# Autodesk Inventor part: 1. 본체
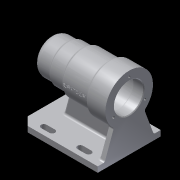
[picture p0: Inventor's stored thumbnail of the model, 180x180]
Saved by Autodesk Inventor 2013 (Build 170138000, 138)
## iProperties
Created: 2017-09
Part Number: 1. 본체
Material: 알루미늄 6061
Document SubType Name: Modeling
Designer: Administrator
Mass: 706.135 g
Surface Area: 708.39 cm^2
Volume: 260.566 cm^3
Density: 2.71 g/cm^3
Author: Administrator
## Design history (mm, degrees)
sketch "스케치1"
  geometry: L1 (-56, 0)-(56, 0); L2 (-56, 0)-(-56, 25); L3 (-56, 25)-(-31, 25); L4 (-31, 25)-(-31, 27); L5 (-31, 27)-(-11, 27); L6 (-11, 27)-(-11, 30); L7 (-11, 30)-(28, 30); L8 (28, 30)-(28, 34); L9 (28, 34)-(56, 34); L10 (56, 34)-(56, 0); L11 (-50, 0)-(-50, 10.5); L12 (-50, 10.5)-(-47, 10.5); L13 (-47, 10.5)-(-47, 16); L14 (-47, 16)-(-43, 16); L15 (-43, 16)-(-43, 17.5); L16 (-43, 17.5)-(-25, 17.5); L17 (-25, 17.5)-(-25, 21); L18 (-25, 21)-(-13, 21); L19 (-13, 21)-(-13, 24); L20 (-13, 24)-(41, 24); L21 (41, 24)-(41, 21); L22 (41, 21)-(56, 21); 2 further points
  constraints: 44 end point, 15 parallel, 6 perpendicular, 2 point on line, 1 coincident, 1 collinear, 1 horizontal, 1 midpoint
  dimensions: "d0" = 112 distance of L1.start L1.end; "d2" = 42 diameter of L22 L1; "d3" = 48 diameter of L20 L1; "d4" = 35 diameter of L16 L1; "d5" = 32 diameter of L14 L1; "d6" = 21 diameter of L12 L1; "d7" = 50 diameter of L3 L1; "d8" = 54 diameter of L5 L1; "d9" = 60 diameter of L7 L1; "d11" = 68 diameter of L9 L1; "d12" = 15 distance between parallel lines of L21 L10; "d13" = 54 distance between parallel lines of L19 L21; "d14" = 12 distance between parallel lines of L17 L19; "d15" = 18 distance between parallel lines of L15 L17; "d16" = 4 distance between parallel lines of L13 L15; "d17" = 3 distance between parallel lines of L11 L13; "d18" = 84 distance between parallel lines of L8 L2; "d19" = 45 distance between parallel lines of L6 L2; "d20" = 25 distance between parallel lines of L4 L2
revolve "회전1" sketch "스케치1" stored, may be unused: angle "d21" = 90 deg
node "작업 평면1"
sketch "스케치2"
  geometry: L1 (-56, 34)-(-56, -34) reference; L2 (56, -45)-(-56, -45); L3 (-56, -45)-(-56, 45); L4 (-56, 45)-(56, 45); L5 (56, 45)-(56, -45); 2 further points
  constraints: 8 end point, 2 parallel, 1 horizontal, 1 horizontal alignment, 1 midpoint, 1 perpendicular, 1 point on line
  dimensions: "d23" = 90 distance between parallel lines of L4 L2; "d25" = 112 distance between parallel lines of L5 L1
extrude "돌출1" join sketch "스케치2" distance "d26" = 8; taper "d27" = 0 deg
sketch "스케치3"
  geometry: L1 (-45, -62)-(45, -62) reference; L2 (21.9, -26.008)-(35, -62); L3 (45, -70)-(45, -62) reference; L4 (0, 0)-(0, -62); L5 (-21.9, -26.008)-(-35, -62); L6 (-35, -62)-(35, -62); L7 (-45, -70)-(-45, -62) reference; A1 r 34 centre (0, 0) between (-21.9, -26.008) and (21.9, -26.008)
  constraints: 8 end point, 2 point on circle, 1 centre point, 1 coincident, 1 collinear, 1 midpoint, 1 point on line, 2 other
  dimensions: "d28" = 10 distance from line of L2.end L3; "d29" = 110 deg angle of L2 L1; "d90" = 10 distance from line of L5.end L7; "d91" = 110 deg angle of L5 L1
extrude "돌출2" join sketch "스케치3" distance "d30" = 8; taper "d31" = 0 deg
sketch "스케치5"
  geometry: L1 (-56, -62)-(56, -62) reference; L2 (-31, -27)-(-11, -27) reference; L3 (-34, -62)-(-24.622, -27); L4 (-56, -70)-(-56, -62) reference; 1 further point
  constraints: 2 end point, 2 point on line
  dimensions: "d34" = 22 distance from line of L3.start L4; "d35" = 105 deg angle of L3 L1
feature "리브1" sketch "스케치5" dims "d36" = 1, "d37" = 8, "d38" = 0, "d39" = 0, "d40" = 1, "d41" = 1
sketch "스케치6" dims "d52" = 10
  geometry: L1 (-56, -45)-(56, -45) reference; L2 (56, -45)-(56, -35) reference; L3 (48, -35)-(48, -4) reference; L4 (20, -30)-(32, -30); L5 (32, -38)-(20, -38); L6 (-20, -38)-(-32, -38); L7 (-32, -30)-(-20, -30); A1 r 4 centre (32, -34) between (32, -38) and (32, -30); A2 r 4 centre (20, -34) between (20, -30) and (20, -38); A3 r 4 centre (-20, -34) between (-20, -38) and (-20, -30); A4 r 4 centre (-32, -34) between (-32, -30) and (-32, -38); 1 further point
  constraints: 8 end point, 8 point on circle, 4 centre point, 4 tangent, 1 horizontal, 1 parallel, 1 perpendicular, 10 other
  dimensions: "d42" = 8 distance between parallel lines of L5 L4; "d44" = 34 vertical distance of A1.centre point (0, 0); "d45" = 24 distance from line of A1.centre L2; "d46" = 12 distance of A2.centre A1.centre; "d49" = 52 distance of A1.centre A3.centre
extrude "돌출3" cut sketch "스케치6" stored distance "d54" = 8; taper "d55" = 0 deg
chamfer "모따기1" distance "d56" = 12; stored, may be unused: second distance "d57" = 2, angle "d58" = 45 deg
fillet "모깎기1" dims "d59" = 3
fillet "모깎기2" dims "d60" = 3
fillet "모깎기3" dims "d61" = 3
fillet "모깎기4" dims "d66" = 9, "d67" = 3, "d68" = 0.3
chamfer "모따기2" distance "d69" = 1; stored, may be unused: second distance "d70" = 2, angle "d71" = 45 deg
fillet "모깎기5" dims "d72" = 3
node "작업 평면2"
sketch "스케치7"
  geometry: L1 (47.5, -24.711)-(47.5, 34) reference; L2 (47.5, -70)-(-52.5, -70) reference; 2 further points
  constraints: 1 other
  dimensions: "d73" = 48 distance from line of point (-0.5, 0) L1; "d74" = 70 distance from line of L2 point (-0.5, 0)
feature "엠보싱1" sketch "스케치7" dims "d0" = 112, "d2" = 42, "d3" = 48, "d4" = 35, "d5" = 32, "d6" = 21, "d7" = 50, "d8" = 54, "d9" = 60, "d11" = 68, "d12" = 15, "d13" = 54, "d14" = 12, "d15" = 18, "d16" = 4, "d17" = 3, "d18" = 84, "d19" = 45, "d20" = 25, "d75" = 0.5, "d76" = 0
sketch "스케치8" dims "d77" = 52
  geometry: C1 r 22 at (45, 70) reference; A1 r 34 centre (45, 70) between (68.353, 45.289) and (21.647, 45.289) reference; 2 further points
  constraints: 2 vertical alignment, 1 coincident, 2 other
hole "구멍1" sketch "스케치8" at (45, 96) diameter "d79" = 3.242; stored, may be unused: countersink angle "d83" = 90 deg, drill point angle "d85" = 118 deg; dims "d80" = 8, "d81" = 4, "d82" = 2, "d84" = 11
node "솔리드1"
mirror "대칭1"
pattern_circular "원형 패턴1" dims angle "d87" = 360 deg
other parameters: "d62" = 0.5, "d63" = 2, "d64" = 0
